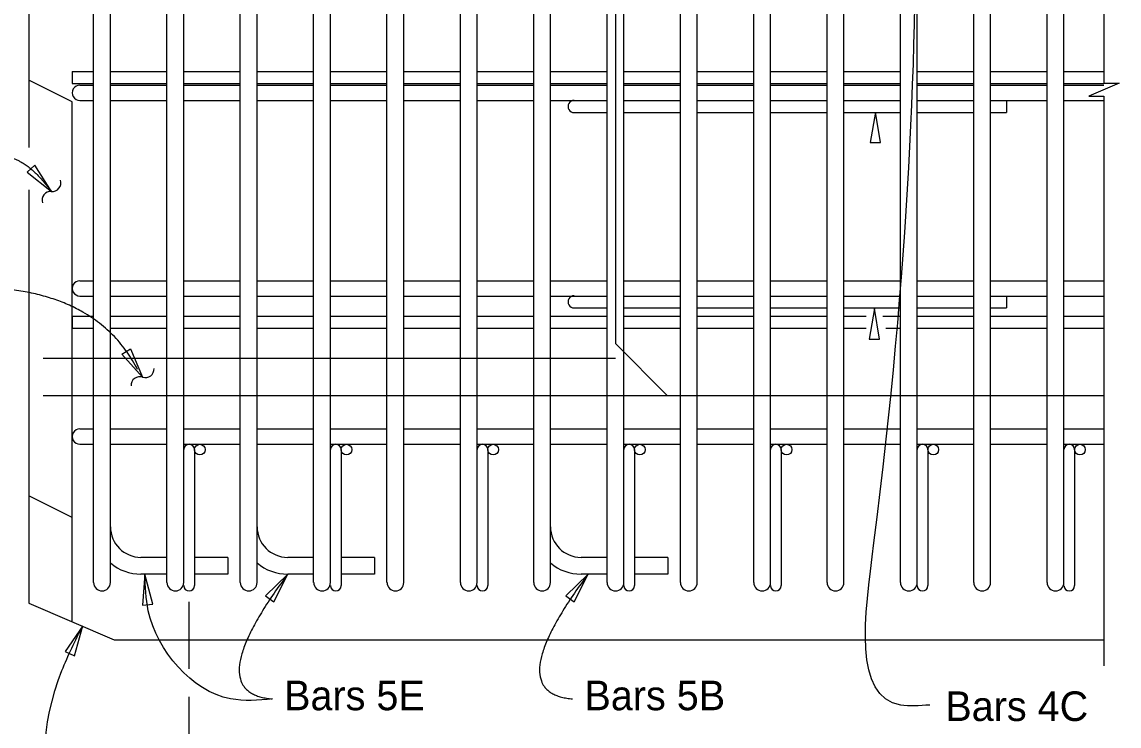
# Model space of a CAD drawing. Extents: x 0 to 20.5, y 0 to 12.9.
# Drawn here: x 12.544 to 16.283, y 4.445 to 6.845 of the extents above; entities that cross this region are included whole.
import ezdxf

# ---------------------------------------------------------------- set-up
doc = ezdxf.new("R2010")
doc.units = 0
for name, color, linetype in [('BeamConc', 7, 'Continuous'), ('BeamConc_h', 7, 'Continuous'), ('Dimension', 7, 'Continuous'), ('Rebar', 7, 'Continuous'), ('TextStructures', 7, 'Continuous')]:
    doc.layers.add(name, color=color, linetype=linetype)

msp = doc.modelspace()

# ---------------------------------------------------------------- linework, layer by layer
at = {"layer": 'BeamConc'}
for p, q in [((12.5667, 9.989), (12.5667, 6.417)), ((12.5667, 6.2725), (12.5667, 4.864)), ((12.7146, 5.1557), (12.5667, 5.2296)), ((12.7146, 4.8006), (12.7146, 5.1557)), ((12.5667, 4.864), (12.8583, 4.739)), ((12.8583, 4.739), (16.2315, 4.739))]:
    msp.add_line(p, q, dxfattribs=at)
at = {"layer": 'BeamConc_h'}
for p, q in [((14.5667, 9.989), (14.5667, 5.7491)), ((12.7146, 6.5723), (12.5667, 6.6463)), ((12.7146, 5.1557), (12.7146, 6.5723)), ((14.7434, 5.5723), (14.5667, 5.7491)), ((12.6155, 5.6991), (14.5667, 5.6991)), ((12.6155, 5.5723), (16.2315, 5.5723))]:
    msp.add_line(p, q, dxfattribs=at)
at = {"layer": 'Dimension'}
for p, q in [((13.1135, 4.6399), (13.1135, 4.8689)), ((13.1135, 3.9086), (13.1135, 4.5448))]:
    msp.add_line(p, q, dxfattribs=at)
msp.add_lwpolyline([(16.2316, 10.0723), (16.2316, 8.3039), (16.2832, 8.3039), (16.1799, 8.2589), (16.2316, 8.2589), (16.2316, 6.6365), (16.2832, 6.6365), (16.1799, 6.5915), (16.2316, 6.5915), (16.2316, 4.6506)], dxfattribs=at)
for points in [[(15.453, 6.5376), (15.4351, 6.4336), (15.4704, 6.4335)], [(12.6441, 6.2667), (12.588, 6.3562), (12.5617, 6.3327)], [(15.4492, 5.8682), (15.4313, 5.7641), (15.4666, 5.764)], [(12.9547, 5.6341), (12.8838, 5.7123), (12.9135, 5.7313)], [(12.9631, 4.963), (12.955, 4.8577), (12.9901, 4.8608)], [(13.4495, 4.963), (13.3739, 4.8892), (13.4024, 4.8684)], [(14.4732, 4.963), (14.3976, 4.8892), (14.4261, 4.8684)], [(12.7512, 4.7864), (12.6911, 4.6996), (12.723, 4.6846)]]:
    msp.add_lwpolyline(points, close=True, dxfattribs=at)
for centre, start, end in [((12.6465, 6.2966), 265.8557, 17.5829), ((12.6422, 6.2372), 85.8557, 197.5829), ((12.9645, 5.6625), 251.3723, 3.0996), ((12.9455, 5.606), 71.3723, 183.0996)]:
    msp.add_arc(centre, 0.0298, start, end, dxfattribs=at)
for points in [[(15.6378, 4.5169), (15.5391, 4.5169), (15.4476, 5.0695), (15.4631, 9.1922)], [(13.3976, 4.538), (13.2548, 4.538), (12.9744, 4.8382), (12.9631, 4.963)], [(13.0401, 3.7405), (12.9732, 3.7456), (12.6713, 4.0535), (12.68, 4.6344), (12.7512, 4.7864)]]:
    msp.add_spline(points, degree=3, dxfattribs=at)
for points in [[(12.4704, 6.3876), (12.5567, 6.3876), (12.6441, 6.2666)], [(12.9381, 5.66), (12.7799, 5.9679), (12.2862, 5.938)], [(13.4495, 4.963), (13.1481, 4.5587), (13.3966, 4.538)], [(14.4732, 4.963), (14.1718, 4.5587), (14.4203, 4.538)]]:
    msp.add_open_spline(points, degree=2, dxfattribs=at)
at = {"layer": 'Rebar'}
for p, q in [((12.788, 4.9343), (12.788, 10.4187)), ((13.288, 4.9343), (13.288, 10.4187)), ((13.538, 4.9343), (13.538, 10.4187)), ((13.788, 4.9343), (13.788, 10.4187)), ((14.038, 4.9343), (14.038, 10.4187)), ((14.288, 4.9343), (14.288, 10.4187)), ((14.5953, 4.9343), (14.5953, 10.4187)), ((14.8453, 4.9343), (14.8453, 10.4187)), ((15.0953, 4.9343), (15.0953, 10.4187)), ((15.3453, 4.9343), (15.3453, 10.4187)), ((15.5953, 4.9343), (15.5953, 10.4187)), ((15.8453, 4.9343), (15.8453, 10.4187)), ((16.0953, 4.9343), (16.0953, 10.4187)), ((12.8453, 4.9343), (12.8453, 9.5422)), ((13.0953, 4.9343), (13.0953, 9.5422)), ((13.3453, 4.9343), (13.3453, 9.5422)), ((13.5953, 4.9343), (13.5953, 9.5422)), ((13.8453, 4.9343), (13.8453, 9.5422)), ((14.0953, 4.9343), (14.0953, 9.5422)), ((14.3453, 4.9343), (14.3453, 9.5422)), ((14.538, 4.9343), (14.538, 9.5422)), ((14.788, 4.9343), (14.788, 9.5422)), ((15.038, 4.9343), (15.038, 9.5422)), ((15.288, 4.9343), (15.288, 9.5422)), ((15.538, 4.9343), (15.538, 9.5422)), ((15.788, 4.9343), (15.788, 9.5422)), ((16.038, 4.9343), (16.038, 9.5422)), ((13.038, 4.9343), (13.038, 9.2971)), ((12.7151, 6.6764), (12.788, 6.6764)), ((12.7151, 6.6764), (12.7151, 6.6348)), ((12.8453, 6.6764), (13.038, 6.6764)), ((13.0953, 6.6764), (13.288, 6.6764)), ((13.3453, 6.6764), (13.538, 6.6764)), ((13.5953, 6.6764), (13.788, 6.6764)), ((13.8453, 6.6764), (14.038, 6.6764)), ((14.0953, 6.6764), (14.288, 6.6764)), ((14.3453, 6.6764), (14.538, 6.6764)), ((14.5953, 6.6764), (14.788, 6.6764)), ((14.8453, 6.6764), (15.038, 6.6764)), ((15.0953, 6.6764), (15.288, 6.6764)), ((15.3453, 6.6764), (15.538, 6.6764)), ((15.5953, 6.6764), (15.788, 6.6764)), ((15.8453, 6.6764), (16.038, 6.6764)), ((16.0953, 6.6764), (16.2315, 6.6764)), ((12.7151, 6.6348), (12.788, 6.6348)), ((12.7411, 6.6296), (12.788, 6.6296)), ((12.8453, 6.6348), (13.038, 6.6348)), ((12.8453, 6.6296), (13.038, 6.6296)), ((13.0953, 6.6348), (13.288, 6.6348)), ((13.0953, 6.6296), (13.288, 6.6296)), ((13.3453, 6.6348), (13.538, 6.6348)), ((13.3453, 6.6296), (13.538, 6.6296)), ((13.5953, 6.6348), (13.788, 6.6348)), ((13.5953, 6.6296), (13.788, 6.6296)), ((13.8453, 6.6348), (14.038, 6.6348)), ((13.8453, 6.6296), (14.038, 6.6296)), ((14.0953, 6.6348), (14.288, 6.6348)), ((14.0953, 6.6296), (14.288, 6.6296)), ((14.3453, 6.6348), (14.538, 6.6348)), ((14.3453, 6.6296), (14.538, 6.6296)), ((14.5953, 6.6348), (14.788, 6.6348)), ((14.5953, 6.6296), (14.788, 6.6296)), ((14.8453, 6.6348), (15.038, 6.6348)), ((14.8453, 6.6296), (15.038, 6.6296)), ((15.0953, 6.6348), (15.288, 6.6348)), ((15.0953, 6.6296), (15.288, 6.6296)), ((15.3453, 6.6348), (15.538, 6.6348)), ((15.3453, 6.6296), (15.538, 6.6296)), ((15.5953, 6.6348), (15.788, 6.6348)), ((15.5953, 6.6296), (15.788, 6.6296)), ((15.8453, 6.6348), (16.038, 6.6348)), ((15.8453, 6.6296), (16.038, 6.6296)), ((16.0953, 6.6348), (16.2315, 6.6348)), ((16.0953, 6.6296), (16.2315, 6.6296)), ((12.7411, 6.5775), (12.788, 6.5775)), ((12.8453, 6.5775), (13.038, 6.5775)), ((13.0953, 6.5775), (13.288, 6.5775)), ((13.3453, 6.5775), (13.538, 6.5775)), ((13.5953, 6.5775), (13.788, 6.5775)), ((13.8453, 6.5775), (14.038, 6.5775)), ((14.0953, 6.5775), (14.288, 6.5775)), ((14.3453, 6.5775), (14.538, 6.5775)), ((14.5953, 6.5775), (14.788, 6.5775)), ((14.8453, 6.5775), (15.038, 6.5775)), ((15.0953, 6.5775), (15.288, 6.5775)), ((15.3453, 6.5775), (15.538, 6.5775)), ((15.5953, 6.5775), (15.788, 6.5775)), ((15.8453, 6.5775), (16.038, 6.5775)), ((15.9, 6.5775), (15.9, 6.5358)), ((16.0953, 6.5775), (16.2315, 6.5775)), ((14.426, 6.5358), (14.538, 6.5358)), ((14.5953, 6.5358), (14.788, 6.5358)), ((14.8453, 6.5358), (15.038, 6.5358)), ((15.0953, 6.5358), (15.288, 6.5358)), ((15.3453, 6.5358), (15.538, 6.5358)), ((15.5953, 6.5358), (15.788, 6.5358)), ((15.8453, 6.5358), (15.9, 6.5358)), ((12.7411, 5.9628), (12.788, 5.9628)), ((12.8453, 5.9628), (13.038, 5.9628)), ((13.0953, 5.9628), (13.288, 5.9628)), ((13.3453, 5.9628), (13.538, 5.9628)), ((13.5953, 5.9628), (13.788, 5.9628)), ((13.8453, 5.9628), (14.038, 5.9628)), ((14.0953, 5.9628), (14.288, 5.9628)), ((14.3453, 5.9628), (14.538, 5.9628)), ((14.5953, 5.9628), (14.788, 5.9628)), ((14.8453, 5.9628), (15.038, 5.9628)), ((15.0953, 5.9628), (15.288, 5.9628)), ((15.3453, 5.9628), (15.538, 5.9628)), ((15.5953, 5.9628), (15.788, 5.9628)), ((15.8453, 5.9628), (16.038, 5.9628)), ((16.0953, 5.9628), (16.2315, 5.9628)), ((12.7411, 5.9108), (12.788, 5.9108)), ((12.8453, 5.9108), (13.038, 5.9108)), ((13.0953, 5.9108), (13.288, 5.9108)), ((13.3453, 5.9108), (13.538, 5.9108)), ((13.5953, 5.9108), (13.788, 5.9108)), ((13.8453, 5.9108), (14.038, 5.9108)), ((14.0953, 5.9108), (14.288, 5.9108)), ((14.3453, 5.9108), (14.538, 5.9108)), ((14.5953, 5.9108), (14.788, 5.9108)), ((14.8453, 5.9108), (15.038, 5.9108)), ((15.0953, 5.9108), (15.288, 5.9108)), ((15.3453, 5.9108), (15.538, 5.9108)), ((15.5953, 5.9108), (15.788, 5.9108)), ((15.8453, 5.9108), (16.038, 5.9108)), ((15.9, 5.9108), (15.9, 5.8701)), ((16.0953, 5.9108), (16.2315, 5.9108)), ((12.7151, 5.8424), (12.788, 5.8424)), ((12.7151, 5.8424), (12.7151, 5.8008)), ((12.8453, 5.8424), (13.038, 5.8424)), ((13.0953, 5.8424), (13.288, 5.8424)), ((13.3453, 5.8424), (13.538, 5.8424)), ((13.5953, 5.8424), (13.788, 5.8424)), ((13.8453, 5.8424), (14.038, 5.8424)), ((14.0953, 5.8424), (14.288, 5.8424)), ((14.3453, 5.8424), (14.538, 5.8424)), ((14.426, 5.8701), (14.538, 5.8701)), ((14.5953, 5.8701), (14.788, 5.8701)), ((14.5953, 5.8424), (14.788, 5.8424)), ((14.8453, 5.8701), (15.038, 5.8701)), ((14.8453, 5.8424), (15.038, 5.8424)), ((15.0953, 5.8701), (15.288, 5.8701)), ((15.0953, 5.8424), (15.288, 5.8424)), ((15.3453, 5.8701), (15.538, 5.8701)), ((15.3453, 5.8424), (15.4215, 5.8424)), ((15.4784, 5.8424), (15.538, 5.8424)), ((15.5953, 5.8701), (15.788, 5.8701)), ((15.5953, 5.8424), (15.788, 5.8424)), ((15.8453, 5.8701), (15.9, 5.8701)), ((15.8453, 5.8424), (16.038, 5.8424)), ((16.0953, 5.8424), (16.2315, 5.8424)), ((12.7151, 5.8008), (12.788, 5.8008)), ((12.8453, 5.8008), (13.038, 5.8008)), ((13.0953, 5.8008), (13.288, 5.8008)), ((13.3453, 5.8008), (13.538, 5.8008)), ((13.5953, 5.8008), (13.788, 5.8008)), ((13.8453, 5.8008), (14.038, 5.8008)), ((14.0953, 5.8008), (14.288, 5.8008)), ((14.3453, 5.8008), (14.538, 5.8008)), ((14.5953, 5.8008), (14.788, 5.8008)), ((14.8453, 5.8008), (15.038, 5.8008)), ((15.0953, 5.8008), (15.288, 5.8008)), ((15.3453, 5.8008), (15.4215, 5.8008)), ((15.4886, 5.8008), (15.538, 5.8008)), ((15.5953, 5.8008), (15.788, 5.8008)), ((15.8453, 5.8008), (16.038, 5.8008)), ((16.0953, 5.8008), (16.2315, 5.8008)), ((12.7411, 5.4577), (12.788, 5.4577)), ((12.8453, 5.4577), (13.038, 5.4577)), ((13.0953, 5.4577), (13.288, 5.4577)), ((13.3453, 5.4577), (13.538, 5.4577)), ((13.5953, 5.4577), (13.788, 5.4577)), ((13.8453, 5.4577), (14.038, 5.4577)), ((14.0953, 5.4577), (14.288, 5.4577)), ((14.3453, 5.4577), (14.538, 5.4577)), ((14.5953, 5.4577), (14.788, 5.4577)), ((14.8453, 5.4577), (15.038, 5.4577)), ((15.0953, 5.4577), (15.288, 5.4577)), ((15.3453, 5.4577), (15.538, 5.4577)), ((15.5953, 5.4577), (15.788, 5.4577)), ((15.8453, 5.4577), (16.038, 5.4577)), ((16.0953, 5.4577), (16.2315, 5.4577)), ((12.7411, 5.4057), (12.788, 5.4057)), ((12.8453, 5.4057), (13.038, 5.4057)), ((13.0953, 5.4057), (13.288, 5.4057)), ((13.1318, 5.3874), (13.1318, 4.9239)), ((13.3453, 5.4057), (13.538, 5.4057)), ((13.5953, 5.4057), (13.788, 5.4057)), ((13.6318, 5.3874), (13.6318, 4.9239)), ((13.8453, 5.4057), (14.038, 5.4057)), ((14.0953, 5.4057), (14.288, 5.4057)), ((14.1318, 5.3874), (14.1318, 4.9239)), ((14.3453, 5.4057), (14.538, 5.4057)), ((14.5953, 5.4057), (14.788, 5.4057)), ((14.6318, 5.3874), (14.6318, 4.9239)), ((14.8453, 5.4057), (15.038, 5.4057)), ((15.0953, 5.4057), (15.288, 5.4057)), ((15.1318, 5.3874), (15.1318, 4.9239)), ((15.3453, 5.4057), (15.538, 5.4057)), ((15.5953, 5.4057), (15.788, 5.4057)), ((15.6318, 5.3874), (15.6318, 4.9239)), ((15.8453, 5.4057), (16.038, 5.4057)), ((16.0953, 5.4057), (16.2315, 5.4057)), ((16.1318, 5.3874), (16.1318, 4.9239)), ((13.038, 5.0202), (12.9495, 5.0202)), ((13.245, 5.0202), (13.1318, 5.0202)), ((13.245, 5.0202), (13.245, 4.963)), ((13.538, 5.0202), (13.4495, 5.0202)), ((13.745, 5.0202), (13.6318, 5.0202)), ((13.745, 5.0202), (13.745, 4.963)), ((14.538, 5.0202), (14.4495, 5.0202)), ((14.745, 5.0202), (14.6318, 5.0202)), ((14.745, 5.0202), (14.745, 4.963)), ((13.038, 4.963), (12.9495, 4.963)), ((13.245, 4.963), (13.1318, 4.963)), ((13.538, 4.963), (13.4495, 4.963)), ((13.745, 4.963), (13.6318, 4.963)), ((14.538, 4.963), (14.4495, 4.963)), ((14.745, 4.963), (14.6318, 4.963))]:
    msp.add_line(p, q, dxfattribs=at)
for centre in [(13.15, 5.3874), (13.65, 5.3874), (14.15, 5.3874), (14.65, 5.3874), (15.15, 5.3874), (15.65, 5.3874), (16.15, 5.3874)]:
    msp.add_circle(centre, 0.0182, dxfattribs=at)
for centre, radius, start, end in [((12.7411, 6.6035), 0.026, 89.99, 270), ((14.426, 6.5566), 0.0208, 89.9887, 269.9987), ((12.7411, 5.9368), 0.026, 89.99, 270), ((14.426, 5.8909), 0.0208, 89.9887, 269.9987), ((12.7411, 5.4317), 0.026, 89.99, 270), ((13.1135, 5.3874), 0.0182, 0, 180), ((13.6135, 5.3874), 0.0182, 0, 180), ((14.1135, 5.3874), 0.0182, 0, 180), ((14.6135, 5.3874), 0.0182, 0, 180), ((15.1135, 5.3874), 0.0182, 0, 180), ((15.6135, 5.3874), 0.0182, 0, 180), ((16.1135, 5.3874), 0.0182, 0, 180), ((12.9495, 5.1244), 0.1042, 180, 270), ((13.4495, 5.1244), 0.1042, 180, 270), ((14.4495, 5.1244), 0.1042, 180, 270), ((12.9495, 5.1244), 0.1615, 229.8222, 270), ((13.4495, 5.1244), 0.1615, 229.8222, 270), ((14.4495, 5.1244), 0.1615, 229.8222, 270), ((12.8167, 4.9343), 0.0286, 180, 0), ((13.0667, 4.9343), 0.0286, 180, 0), ((13.1135, 4.9239), 0.0182, 180, 0), ((13.3167, 4.9343), 0.0286, 180, 0), ((13.5667, 4.9343), 0.0286, 180, 0), ((13.6135, 4.9239), 0.0182, 180, 0), ((13.8167, 4.9343), 0.0286, 180, 0), ((14.0667, 4.9343), 0.0286, 180, 0), ((14.1135, 4.9239), 0.0182, 180, 0), ((14.3167, 4.9343), 0.0286, 180, 0), ((14.5667, 4.9343), 0.0286, 180, 0), ((14.6135, 4.9239), 0.0182, 180, 0), ((14.8167, 4.9343), 0.0286, 180, 0), ((15.0667, 4.9343), 0.0286, 180, 0), ((15.1135, 4.9239), 0.0182, 180, 0), ((15.3167, 4.9343), 0.0286, 180, 0), ((15.5667, 4.9343), 0.0286, 180, 0), ((15.6135, 4.9239), 0.0182, 180, 0), ((15.8167, 4.9343), 0.0286, 180, 0), ((16.0667, 4.9343), 0.0286, 180, 0), ((16.1135, 4.9239), 0.0182, 180, 0)]:
    msp.add_arc(centre, radius, start, end, dxfattribs=at)

# ---------------------------------------------------------------- texts
at = {"layer": 'TextStructures'}
for s, p in [('Bars 5E', (13.4373, 4.4992)), ('Bars 5B', (14.461, 4.4992)), ('Bars 4C', (15.6911, 4.4626))]:
    msp.add_text(s, height=0.1008, dxfattribs=at).set_placement(p)

doc.saveas('drawing.dxf')
